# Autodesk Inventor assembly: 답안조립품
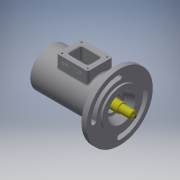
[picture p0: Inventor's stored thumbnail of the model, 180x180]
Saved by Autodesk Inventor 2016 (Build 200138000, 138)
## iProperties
Created: 2017-05
Part Number: 답안조립품
Material: 일반
Document SubType Name: Assembly
Designer: USER
Author: USER
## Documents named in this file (5)
- C:\Users\USER\Desktop\470508V1005\답안조립품.iam
- C:\Users\USER\Desktop\470508V1005\본체.ipt
- C:\Users\USER\Desktop\470508V1005\부시1.ipt
- C:\Users\USER\Desktop\470508V1005\축.ipt
- C:\Users\USER\Desktop\470508V1005\키 4 x 4 x 18.ipt
